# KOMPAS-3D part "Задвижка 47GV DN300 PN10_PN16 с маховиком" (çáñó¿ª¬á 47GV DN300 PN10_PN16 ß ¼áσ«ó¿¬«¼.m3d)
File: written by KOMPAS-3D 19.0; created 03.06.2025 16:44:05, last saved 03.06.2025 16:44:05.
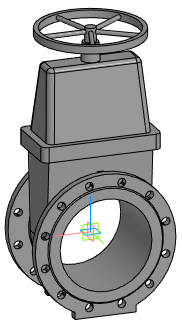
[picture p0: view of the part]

Document properties: Автор: Евгений; Полное имя файла: E:\Dendor Работа Сачек\3D для проекитирвщиков\2.1 Тип 47GV, 47GV.Z Задвижка клиновая фланцевая с обрезиненным клином\stp_Тип 47GV. Задвижка DN40-DN350 с маховиком\Задвижка 47GV DN300 PN10_PN16 с маховиком.m3d

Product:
- Part/product: Задвижка 47GV DN300 PN10_PN16 с маховиком

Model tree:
1. Операция без истории:1  (labels: Задвижка 47GV DN300 PN10_PN16 с маховиком)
